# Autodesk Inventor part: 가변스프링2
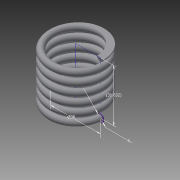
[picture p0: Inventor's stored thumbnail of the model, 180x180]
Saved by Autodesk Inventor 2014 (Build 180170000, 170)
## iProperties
Created: 2017-03
Part Number: 가변스프링2
Material: 강철, 탄소
Document SubType Name: Modeling
Designer: SEC
Density: 1 g/cm^3
Appearance: 반연마
Mass: 6.91589 g
Surface Area: 70.6396 cm^2
Volume: 6.91589 cm^3
Author: SEC
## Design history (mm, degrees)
sketch "스케치1"
  geometry: L1 (0, 0)-(15, 0); L2 (15, 0)-(15, 31.632); L3 (15, 31.632)-(0, 31.632); L4 (0, 31.632)-(0, 0); C1 r 2 at (15, 0)
  constraints: 8 end point, 2 parallel, 1 centre point, 1 coincident, 1 horizontal, 1 perpendicular
  dimensions: "d0" = 30 diameter of L2 L4; "d1" = 31.63241 distance of L1.end L2.end (derived); "d2" = 4 diameter of C1
feature "코일1" pitch "d3" = 10; turns "d5" = 6; dims "d4" = 31.63241 (= d1), "d6" = 0, angle "d7" = 90 deg, angle "d8" = 90 deg, "d9" = 0, "d10" = 0
sketch "스케치2"
  geometry: L1 (-13, 0)-(-17, 0) reference; 1 further point
  constraints: 1 horizontal alignment
extrude "돌출1" cut sketch "스케치2" stored distance "d11" = 10; taper "d12" = 0 deg
node "작업 평면1"
sketch "스케치3"
  geometry: L1 (-2, 0)-(2, 0) reference; 1 further point
  constraints: 1 horizontal alignment
extrude "돌출2" cut sketch "스케치3" stored distance "d13" = 10; taper "d14" = 0 deg
node "솔리드1"
node "절단 모서리 투영1"
node "절단 모서리 투영2"
